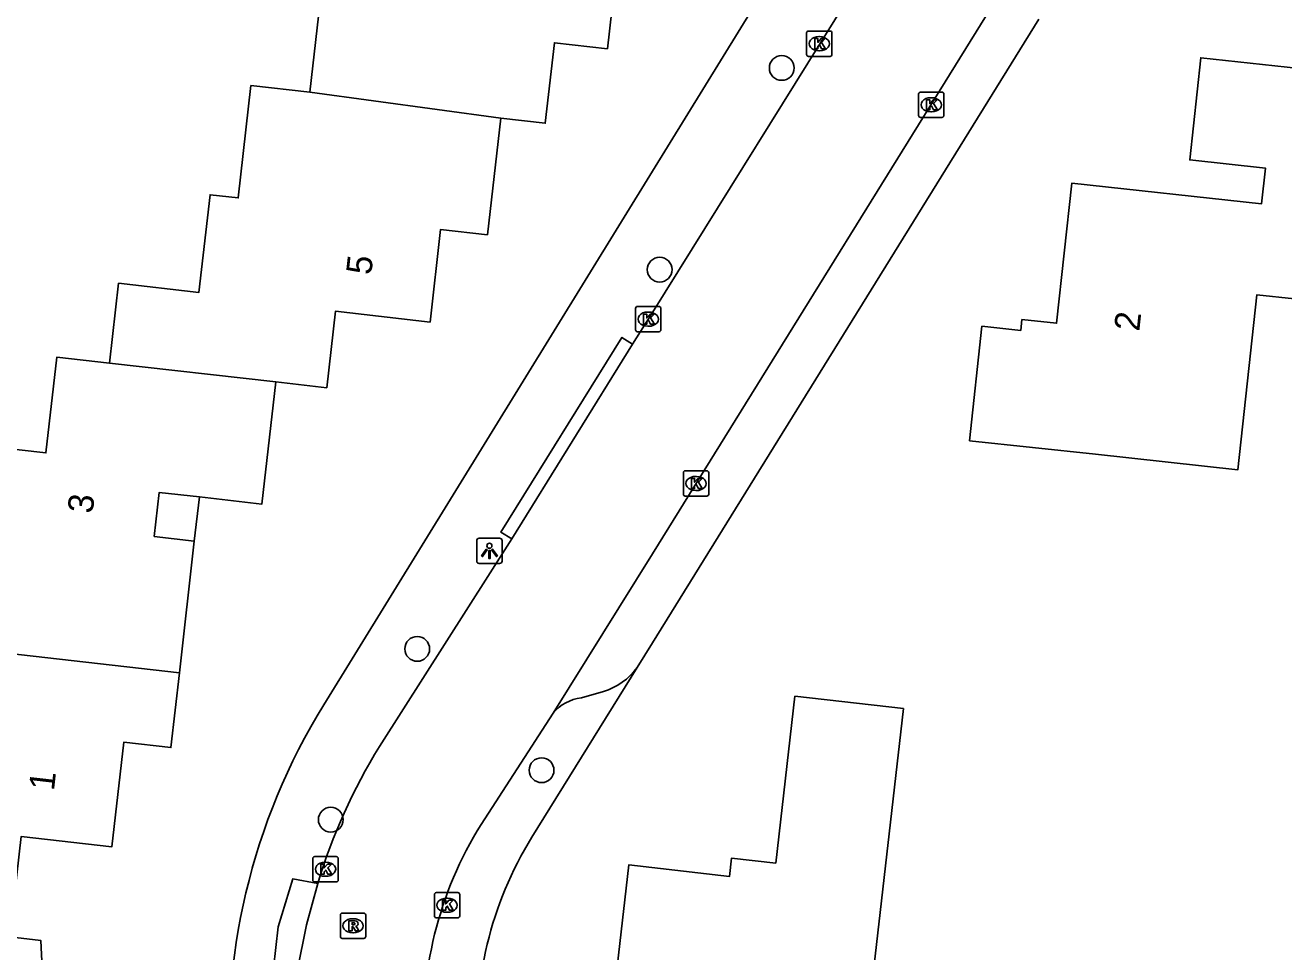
# Model space of a CAD drawing. Extents: x 162398 to 163643, y 386453 to 387397.
# Drawn here: x 162975.24 to 163024.93, y 386583.81 to 386620.41 of the extents above; entities that cross this region are included whole.
import ezdxf

# ---------------------------------------------------------------- set-up
doc = ezdxf.new("R2010")
doc.units = 0
for name, color, linetype in [('IMGEO_Boom', 7, 'Continuous'), ('IMGEO_Kolk', 7, 'Continuous'), ('IMGEO_Lichtpunt', 7, 'Continuous'), ('IMGEO_Pand', 7, 'Continuous'), ('IMGEO_Pand_nummerreeks', 7, 'Continuous'), ('IMGEO_Pand_overbouw', 7, 'Continuous'), ('IMGEO_Parkeervlak_open', 7, 'Continuous'), ('IMGEO_Rijbaan_lokaal_open', 7, 'Continuous'), ('IMGEO_Rioolput', 7, 'Continuous'), ('IMGEO_Voetpad_open', 7, 'Continuous')]:
    doc.layers.add(name, color=color, linetype=linetype)

msp = doc.modelspace()

# ---------------------------------------------------------------- linework, layer by layer
at = {"layer": 'IMGEO_Boom'}
for centre in [(163005.108, 386618.72), (163000.288, 386610.754), (162990.719, 386595.774), (162995.628, 386590.981), (162987.307, 386589.03)]:
    msp.add_circle(centre, 0.489, dxfattribs=at)
at = {"layer": 'IMGEO_Kolk'}
for p, q in [((163006.165, 386620.178), (163007.017, 386620.178)), ((163006.09, 386619.252), (163006.09, 386620.104)), ((163006.578, 386619.958), (163006.603, 386619.958)), ((163007.091, 386620.104), (163007.091, 386619.252)), ((163007.017, 386619.178), (163006.165, 386619.178)), ((163006.601, 386619.398), (163006.576, 386619.398)), ((163010.506, 386616.838), (163010.506, 386617.69)), ((163010.581, 386617.764), (163011.433, 386617.764)), ((163011.507, 386617.69), (163011.507, 386616.838)), ((163010.994, 386617.544), (163011.019, 386617.544)), ((163011.433, 386616.764), (163010.581, 386616.764)), ((163011.017, 386616.984), (163010.992, 386616.984)), ((162999.335, 386608.372), (162999.335, 386609.224)), ((162999.41, 386609.298), (163000.262, 386609.298)), ((163000.336, 386609.224), (163000.336, 386608.372)), ((162999.823, 386609.078), (162999.848, 386609.078)), ((163000.262, 386608.298), (162999.41, 386608.298)), ((162999.846, 386608.518), (162999.821, 386608.518)), ((163001.226, 386601.881), (163001.226, 386602.733)), ((163001.301, 386602.807), (163002.153, 386602.807)), ((163002.227, 386602.733), (163002.227, 386601.881)), ((163001.714, 386602.587), (163001.739, 386602.587)), ((163002.153, 386601.807), (163001.301, 386601.807)), ((163001.737, 386602.027), (163001.712, 386602.027)), ((162986.598, 386586.645), (162986.598, 386587.497)), ((162986.673, 386587.571), (162987.525, 386587.571)), ((162987.086, 386587.351), (162987.111, 386587.351)), ((162987.599, 386587.497), (162987.599, 386586.645)), ((162987.525, 386586.571), (162986.673, 386586.571)), ((162987.109, 386586.791), (162987.084, 386586.791)), ((162991.399, 386585.224), (162991.399, 386586.076)), ((162991.474, 386586.15), (162992.326, 386586.15)), ((162991.887, 386585.93), (162991.912, 386585.93)), ((162992.4, 386586.076), (162992.4, 386585.224)), ((162991.91, 386585.37), (162991.885, 386585.37)), ((162992.326, 386585.15), (162991.474, 386585.15))]:
    msp.add_line(p, q, dxfattribs=at)
for points in [[(163006.165, 386620.178), (163007.017, 386620.178)], [(163006.09, 386619.252), (163006.09, 386620.104)], [(163006.411, 386619.878), (163006.534, 386619.878), (163006.534, 386619.727), (163006.664, 386619.878), (163006.828, 386619.878), (163006.682, 386619.727), (163006.835, 386619.478), (163006.683, 386619.478), (163006.598, 386619.642), (163006.534, 386619.575), (163006.534, 386619.478), (163006.411, 386619.478), (163006.411, 386619.878)], [(163007.091, 386620.104), (163007.091, 386619.252)], [(163007.017, 386619.178), (163006.165, 386619.178)], [(163010.506, 386616.838), (163010.506, 386617.69)], [(163010.581, 386617.764), (163011.433, 386617.764)], [(163011.507, 386617.69), (163011.507, 386616.838)], [(163010.827, 386617.464), (163010.95, 386617.464), (163010.95, 386617.313), (163011.08, 386617.464), (163011.244, 386617.464), (163011.098, 386617.313), (163011.251, 386617.064), (163011.099, 386617.064), (163011.014, 386617.228), (163010.95, 386617.161), (163010.95, 386617.064), (163010.827, 386617.064), (163010.827, 386617.464)], [(163011.433, 386616.764), (163010.581, 386616.764)], [(162999.335, 386608.372), (162999.335, 386609.224)], [(162999.41, 386609.298), (163000.262, 386609.298)], [(163000.336, 386609.224), (163000.336, 386608.372)], [(162999.656, 386608.998), (162999.779, 386608.998), (162999.779, 386608.847), (162999.909, 386608.998), (163000.073, 386608.998), (162999.927, 386608.847), (163000.08, 386608.598), (162999.928, 386608.598), (162999.843, 386608.762), (162999.779, 386608.695), (162999.779, 386608.598), (162999.656, 386608.598), (162999.656, 386608.998)], [(163000.262, 386608.298), (162999.41, 386608.298)], [(163001.226, 386601.881), (163001.226, 386602.733)], [(163001.301, 386602.807), (163002.153, 386602.807)], [(163002.227, 386602.733), (163002.227, 386601.881)], [(163001.547, 386602.507), (163001.67, 386602.507), (163001.67, 386602.356), (163001.8, 386602.507), (163001.964, 386602.507), (163001.818, 386602.356), (163001.971, 386602.107), (163001.819, 386602.107), (163001.734, 386602.271), (163001.67, 386602.204), (163001.67, 386602.107), (163001.547, 386602.107), (163001.547, 386602.507)], [(163002.153, 386601.807), (163001.301, 386601.807)], [(162986.598, 386586.645), (162986.598, 386587.497)], [(162986.673, 386587.571), (162987.525, 386587.571)], [(162987.599, 386587.497), (162987.599, 386586.645)], [(162986.919, 386587.271), (162987.042, 386587.271), (162987.042, 386587.12), (162987.172, 386587.271), (162987.336, 386587.271), (162987.19, 386587.12), (162987.343, 386586.871), (162987.191, 386586.871), (162987.106, 386587.035), (162987.042, 386586.968), (162987.042, 386586.871), (162986.919, 386586.871), (162986.919, 386587.271)], [(162987.525, 386586.571), (162986.673, 386586.571)], [(162991.399, 386585.224), (162991.399, 386586.076)], [(162991.474, 386586.15), (162992.326, 386586.15)], [(162991.72, 386585.85), (162991.843, 386585.85), (162991.843, 386585.699), (162991.973, 386585.85), (162992.137, 386585.85), (162991.991, 386585.699), (162992.144, 386585.45), (162991.992, 386585.45), (162991.907, 386585.614), (162991.843, 386585.547), (162991.843, 386585.45), (162991.72, 386585.45), (162991.72, 386585.85)], [(162992.4, 386586.076), (162992.4, 386585.224)], [(162992.326, 386585.15), (162991.474, 386585.15)]]:
    msp.add_lwpolyline(points, dxfattribs=at)
for centre, start, end in [((163006.167, 386620.102), 91.552, 178.448), ((163006.167, 386620.102), 91.552, 178.448), ((163007.015, 386620.102), 1.552, 88.448), ((163007.015, 386620.102), 1.552, 88.448), ((163006.167, 386619.254), 181.552, 268.448), ((163006.167, 386619.254), 181.552, 268.448), ((163007.015, 386619.254), 271.552, 358.448), ((163007.015, 386619.254), 271.552, 358.448), ((163010.583, 386617.688), 91.552, 178.448), ((163010.583, 386617.688), 91.552, 178.448), ((163011.431, 386617.688), 1.552, 88.448), ((163011.431, 386617.688), 1.552, 88.448), ((163010.583, 386616.84), 181.552, 268.448), ((163010.583, 386616.84), 181.552, 268.448), ((163011.431, 386616.84), 271.552, 358.448), ((163011.431, 386616.84), 271.552, 358.448), ((162999.412, 386609.222), 91.552, 178.448), ((162999.412, 386609.222), 91.552, 178.448), ((163000.26, 386609.222), 1.552, 88.448), ((163000.26, 386609.222), 1.552, 88.448), ((162999.412, 386608.374), 181.552, 268.448), ((162999.412, 386608.374), 181.552, 268.448), ((163000.26, 386608.374), 271.552, 358.448), ((163000.26, 386608.374), 271.552, 358.448), ((163001.303, 386602.731), 91.552, 178.448), ((163001.303, 386602.731), 91.552, 178.448), ((163002.151, 386602.731), 1.552, 88.448), ((163002.151, 386602.731), 1.552, 88.448), ((163001.303, 386601.883), 181.552, 268.448), ((163001.303, 386601.883), 181.552, 268.448), ((163002.151, 386601.883), 271.552, 358.448), ((163002.151, 386601.883), 271.552, 358.448), ((162986.675, 386587.495), 91.552, 178.448), ((162986.675, 386587.495), 91.552, 178.448), ((162987.523, 386587.495), 1.552, 88.448), ((162987.523, 386587.495), 1.552, 88.448), ((162986.675, 386586.647), 181.552, 268.448), ((162986.675, 386586.647), 181.552, 268.448), ((162987.523, 386586.647), 271.552, 358.448), ((162987.523, 386586.647), 271.552, 358.448), ((162991.476, 386586.074), 91.552, 178.448), ((162991.476, 386586.074), 91.552, 178.448), ((162992.324, 386586.074), 1.552, 88.448), ((162992.324, 386586.074), 1.552, 88.448), ((162991.476, 386585.226), 181.552, 268.448), ((162991.476, 386585.226), 181.552, 268.448), ((162992.324, 386585.226), 271.552, 358.448), ((162992.324, 386585.226), 271.552, 358.448)]:
    msp.add_arc(centre, 0.0765, start, end, dxfattribs=at)
for centre, major_axis, ratio, start_param, end_param in [((163006.577, 386619.678), (-0.387, 0.002), 0.722429, 4.712389, 7.853982), ((163006.602, 386619.678), (-0.39, 0.002), 0.717154, 1.570796, 4.712389), ((163010.993, 386617.264), (-0.387, 0.002), 0.722429, 4.712389, 7.853982), ((163011.018, 386617.264), (-0.39, 0.002), 0.717154, 1.570796, 4.712389), ((162999.822, 386608.798), (-0.387, 0.002), 0.722429, 4.712389, 7.853982), ((162999.847, 386608.798), (-0.39, 0.002), 0.717154, 1.570796, 4.712389), ((163001.713, 386602.307), (-0.387, 0.002), 0.722429, 4.712389, 7.853982), ((163001.738, 386602.307), (-0.39, 0.002), 0.717154, 1.570796, 4.712389), ((162987.085, 386587.071), (-0.387, 0.002), 0.722429, 4.712389, 7.853982), ((162987.11, 386587.071), (-0.39, 0.002), 0.717154, 1.570796, 4.712389), ((162991.886, 386585.65), (-0.387, 0.002), 0.722429, 4.712389, 7.853982), ((162991.911, 386585.65), (-0.39, 0.002), 0.717154, 1.570796, 4.712389)]:
    msp.add_ellipse(centre, major_axis=major_axis, ratio=ratio, start_param=start_param, end_param=end_param, dxfattribs=at)
at = {"layer": 'IMGEO_Lichtpunt'}
for p, q in [((162993.071, 386600.049), (162993.071, 386599.242)), ((162993.071, 386600.049), (162993.071, 386599.242)), ((162993.973, 386600.144), (162993.165, 386600.144)), ((162993.973, 386600.144), (162993.165, 386600.144)), ((162994.067, 386599.242), (162994.067, 386600.049)), ((162994.067, 386599.242), (162994.067, 386600.049)), ((162993.165, 386599.148), (162993.973, 386599.148)), ((162993.165, 386599.148), (162993.973, 386599.148))]:
    msp.add_line(p, q, dxfattribs=at)
for points in [[(162993.445, 386599.713), (162993.484, 386599.685), (162993.296, 386599.423), (162993.258, 386599.45), (162993.445, 386599.713)], [(162993.547, 386599.665), (162993.594, 386599.665), (162993.594, 386599.343), (162993.547, 386599.343), (162993.547, 386599.665)], [(162993.657, 386599.685), (162993.695, 386599.712), (162993.882, 386599.45), (162993.843, 386599.422), (162993.657, 386599.685)]]:
    msp.add_lwpolyline(points, dxfattribs=at)
msp.add_circle((162993.57, 386599.847), 0.0994, dxfattribs=at)
for centre, start, end in [((162993.165, 386600.049), 90, 180), ((162993.165, 386600.049), 90, 180), ((162993.973, 386600.049), 0, 90), ((162993.973, 386600.049), 0, 90), ((162993.165, 386599.242), 180, 270), ((162993.165, 386599.242), 180, 270), ((162993.973, 386599.242), 270, 0), ((162993.973, 386599.242), 270, 360)]:
    msp.add_arc(centre, 0.0946, start, end, dxfattribs=at)
at = {"layer": 'IMGEO_Pand'}
for points in [[(162986.481, 386617.76), (162986.942, 386621.82), (162984.888, 386622.053), (162985.358, 386626.198), (162986.33, 386626.088), (162986.685, 386629.222), (162988.151, 386629.056)], [(162992.971, 386628.599), (162992.606, 386625.428), (162998.818, 386624.724), (162998.224, 386619.481), (162996.135, 386619.718), (162995.774, 386616.533), (162994.015, 386616.732)], [(163026.833, 386609.438), (163023.863, 386609.759), (163023.116, 386602.852), (163017.494, 386603.46), (163012.522, 386603.997), (163013.01, 386608.517), (163014.544, 386608.351), (163014.591, 386608.783), (163015.958, 386608.635), (163016.556, 386614.165), (163024.05, 386613.355), (163024.202, 386614.764), (163021.21, 386615.088), (163021.646, 386619.122), (163027.975, 386618.438)], [(162978.575, 386607.056), (162978.932, 386610.213), (162982.104, 386609.853), (162982.541, 386613.71), (162983.653, 386613.584), (162984.156, 386618.023), (162986.481, 386617.76)], [(162986.481, 386617.76), (162994.015, 386616.732)], [(162994.015, 386616.732), (162993.493, 386612.131), (162991.642, 386612.341), (162991.228, 386608.683), (162987.489, 386609.107), (162987.147, 386606.091), (162985.137, 386606.319)], [(162970.808, 386596.022), (162970.846, 386596.36), (162970.913, 386596.952), (162971.713, 386604.006), (162976.062, 386603.513), (162976.49, 386607.292), (162978.575, 386607.056)], [(162978.575, 386607.056), (162985.137, 386606.319)], [(162985.137, 386606.319), (162984.591, 386601.496), (162982.119, 386601.776), (162980.538, 386601.955), (162980.341, 386600.214), (162981.921, 386600.035), (162981.331, 386594.829)], [(162970.808, 386596.022), (162981.331, 386594.829)], [(162981.331, 386594.829), (162980.996, 386591.874), (162979.134, 386592.085), (162978.667, 386587.962), (162975.09, 386588.368), (162974.641, 386584.395)], [(163009.917, 386593.413), (163008.329, 386579.606), (163005.77, 386579.901), (163004.964, 386572.892), (163001.314, 386573.311), (163001.266, 386572.892), (163000, 386573.038), (162998.149, 386573.251), (162998.203, 386573.725), (162997.532, 386573.802), (162998.668, 386583.682), (162999.078, 386587.246), (163003.047, 386586.79), (163003.13, 386587.513), (163004.87, 386587.313), (163005.628, 386593.906), (163009.917, 386593.413)], [(162974.641, 386584.395), (162975.858, 386584.257), (162976.095, 386579.343), (162968.413, 386580.213), (162968.957, 386585.013)]]:
    msp.add_lwpolyline(points, dxfattribs=at)
at = {"layer": 'IMGEO_Pand_overbouw'}
msp.add_lwpolyline([(162982.119, 386601.776), (162980.538, 386601.955), (162980.341, 386600.214), (162981.921, 386600.035)], close=True, dxfattribs=at)
at = {"layer": 'IMGEO_Parkeervlak_open'}
msp.add_lwpolyline([(163015.257, 386620.642), (163000, 386596.016), (162999.395, 386595.039)], dxfattribs=at)
at = {"layer": 'IMGEO_Rijbaan_lokaal_open'}
for points in [[(162996.086, 386593.237), (163000, 386599.532), (163015.235, 386624.111)], [(163008.205, 386622.242), (163000, 386609.064), (162999.223, 386607.813)], [(162999.223, 386607.813), (162994.449, 386600.121)], [(162994.449, 386600.121), (162989.231, 386591.917)], [(162996.086, 386593.237), (162993.242, 386588.843)], [(162986.792, 386586.51), (162986.345, 386584.869), (162985.979, 386583.049), (162985.823, 386581.259), (162985.89, 386579.268)]]:
    msp.add_lwpolyline(points, dxfattribs=at)
for centre, radius, start, end in [((163009.002, 386579.745), 23.218, 148.3818, 163.0597), ((163006.059, 386580.87), 15.095, 148.1163, 184.0381)]:
    msp.add_arc(centre, radius, start, end, dxfattribs=at)
at = {"layer": 'IMGEO_Rioolput'}
for p, q in [((162987.687, 386584.41), (162987.687, 386585.262)), ((162987.762, 386585.336), (162988.614, 386585.336)), ((162988.175, 386585.116), (162988.2, 386585.116)), ((162988.688, 386585.262), (162988.688, 386584.41)), ((162988.198, 386584.556), (162988.173, 386584.556)), ((162988.614, 386584.336), (162987.762, 386584.336))]:
    msp.add_line(p, q, dxfattribs=at)
for points in [[(162987.687, 386584.41), (162987.687, 386585.262)], [(162987.762, 386585.336), (162988.614, 386585.336)], [(162988.276, 386585.034), (162988.024, 386585.036), (162988.024, 386584.636)], [(162988.202, 386584.955), (162988.148, 386584.955), (162988.148, 386584.874)], [(162988.148, 386584.874), (162988.2, 386584.874)], [(162988.688, 386585.262), (162988.688, 386584.41)], [(162988.024, 386584.636), (162988.148, 386584.636), (162988.148, 386584.798), (162988.159, 386584.798)], [(162988.206, 386584.769), (162988.277, 386584.636), (162988.417, 386584.636), (162988.352, 386584.762)], [(162988.614, 386584.336), (162987.762, 386584.336)]]:
    msp.add_lwpolyline(points, dxfattribs=at)
for centre, radius, start, end in [((162987.764, 386585.26), 0.0765, 91.552, 178.448), ((162987.764, 386585.26), 0.0765, 91.552, 178.448), ((162988.184, 386585.063), 0.19, 274.7715, 282.9687), ((162988.208, 386584.859), 0.0964, 77.0061, 93.1865), ((162988.222, 386584.916), 0.0378, 276.6634, 79.6772), ((162988.275, 386584.924), 0.109, 350.3612, 89.416), ((162988.273, 386584.924), 0.112, 277.5842, 350.9817), ((162988.612, 386585.26), 0.0765, 1.552, 88.448), ((162988.612, 386585.26), 0.0765, 1.552, 88.448), ((162987.764, 386584.412), 0.0765, 181.552, 268.448), ((162987.764, 386584.412), 0.0765, 181.552, 268.448), ((162988.158, 386584.745), 0.0533, 26.0293, 88.6989), ((162988.257, 386584.709), 0.108, 29.5134, 73.7905), ((162988.612, 386584.412), 0.0765, 271.552, 358.448), ((162988.612, 386584.412), 0.0765, 271.552, 358.448)]:
    msp.add_arc(centre, radius, start, end, dxfattribs=at)
for centre, major_axis, ratio, start_param, end_param in [((162988.174, 386584.836), (-0.387, 0.002), 0.722429, 4.712389, 7.853982), ((162988.199, 386584.836), (-0.39, 0.002), 0.717154, 1.570796, 4.712389)]:
    msp.add_ellipse(centre, major_axis=major_axis, ratio=ratio, start_param=start_param, end_param=end_param, dxfattribs=at)
at = {"layer": 'IMGEO_Voetpad_open'}
for points in [[(163016.213, 386640.977), (163000, 386614.638), (162987.029, 386593.566)], [(162994.449, 386600.121), (162994.025, 386600.384), (162998.799, 386608.076), (162999.223, 386607.813)], [(162995.246, 386588.336), (162999.395, 386595.039)], [(162998.074, 386594.092), (162997.198, 386593.838)], [(162985.89, 386579.268), (162984.942, 386579.186), (162984.861, 386581.535), (162985.233, 386584.802), (162985.806, 386586.689), (162986.792, 386586.51)]]:
    msp.add_lwpolyline(points, dxfattribs=at)
for centre, radius, start, end in [((162997.321, 386596.537), 2.558, 287.1129, 324.1592), ((162997.385, 386592.163), 1.685, 96.3587, 140.4209), ((163008.512, 386580.334), 25.231, 148.3699, 185.0018), ((163007.523, 386580.738), 14.438, 148.2457, 184.7781)]:
    msp.add_arc(centre, radius, start, end, dxfattribs=at)

# ---------------------------------------------------------------- texts
at = {"layer": 'IMGEO_Pand_nummerreeks'}
for s, rotation, p in [('5', 83.5429, (162988.9, 386610.521)), ('2', 83.8282, (163019.22, 386608.296)), ('3', 83.543, (162977.905, 386601.095)), ('1', 83.5372, (162976.379, 386590.148))]:
    msp.add_text(s, height=1, rotation=rotation, dxfattribs=at).set_placement(p)

doc.saveas('drawing.dxf')
